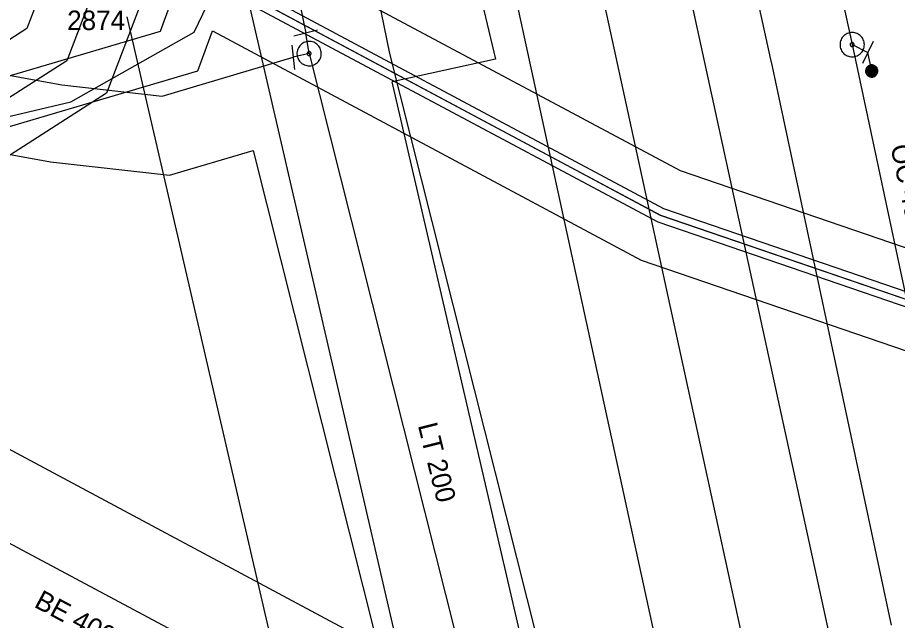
# Model space of a CAD drawing. Extents: x -762993 to -761845, y -975230 to -974501.
# Drawn here: x -762287.32 to -762269.27, y -974997.12 to -974984.74 of the extents above; entities that cross this region are included whole.
import ezdxf

# ---------------------------------------------------------------- set-up
doc = ezdxf.new("R2010")
doc.units = 0
for name, color, linetype in [('IS_CETIN_chranicka', 7, 'Continuous'), ('IS_CETIN_OP', 7, 'Continuous'), ('IS_CETIN_podzem optika zam', 7, 'Continuous'), ('IS_CETIN_podzem out of order', 7, 'Continuous'), ('IS_CEZ-T_parovod', 7, 'Continuous'), ('IS_CEZ-T_parovod OP', 7, 'Continuous'), ('IS_CRA_podzem telekomunikace', 7, 'Continuous'), ('IS_DPmUL_OP', 7, 'Continuous'), ('IS_DPmUL_trakce anotace', 7, 'Continuous'), ('IS_DPmUL_VO vedeni podzem', 7, 'Continuous'), ('IS_SCVK_kanalizace anotace', 7, 'Continuous'), ('IS_SCVK_kanalizace jednotna', 7, 'Continuous'), ('IS_SCVK_kanalizace OP', 7, 'Continuous'), ('IS_SCVK_vodovod anotace', 7, 'Continuous'), ('IS_SCVK_vodovod OP', 7, 'Continuous'), ('IS_SCVK_vodovod privadec', 7, 'Continuous'), ('IS_SCVK_vodovod znaky', 7, 'Continuous')]:
    doc.layers.add(name, color=color, linetype=linetype)

msp = doc.modelspace()

# ---------------------------------------------------------------- linework, layer by layer
at = {"layer": 'IS_CETIN_chranicka'}
for points in [[(-762286.819, -974981.848), (-762283.199, -974983.778), (-762274.07, -974988.662), (-762260.489, -974993.315), (-762251.575, -974995.272), (-762242.453, -974996.331)], [(-762286.961, -974982.112), (-762283.341, -974984.042), (-762274.19, -974988.938), (-762260.571, -974993.605), (-762251.625, -974995.568), (-762242.487, -974996.629)]]:
    msp.add_lwpolyline(points, dxfattribs=at)
at = {"layer": 'IS_CETIN_OP'}
for points in [[(-762282.633, -974983.117), (-762273.729, -974987.88), (-762260.26, -974992.495), (-762251.435, -974994.432), (-762246.779, -974994.973)], [(-762299.477, -974986.662), (-762293.233, -974988.677), (-762283.623, -974985.836), (-762283.324, -974985.015)], [(-762283.324, -974985.015), (-762274.531, -974989.72), (-762260.8, -974994.425), (-762251.765, -974996.408), (-762246.45, -974997.025)]]:
    msp.add_lwpolyline(points, dxfattribs=at)
at = {"layer": 'IS_CETIN_podzem optika zam'}
for points in [[(-762377.62, -974954.57), (-762366.77, -974958.38), (-762363.37, -974959.59), (-762350.74, -974963.98), (-762348.95, -974964.65), (-762339.36, -974968.07), (-762336.01, -974969.53), (-762326.29, -974972.95), (-762323.74, -974973.76), (-762321.62, -974974.46), (-762319.68, -974975.34), (-762318.84, -974976.94), (-762306.74, -974981.28), (-762300.75, -974982.76), (-762292.38, -974985.64), (-762290.68, -974986.06), (-762288.13, -974984.96), (-762286.9, -974983.04), (-762287.05, -974982.43), (-762287.36, -974981.94), (-762286.89, -974981.98), (-762283.27, -974983.91), (-762274.13, -974988.8), (-762260.53, -974993.46)], [(-762299.17, -974985.71), (-762293.22, -974987.63), (-762284.39, -974985.02), (-762281.56, -974977.25), (-762281.87, -974976.53), (-762282.79, -974972.08)]]:
    msp.add_lwpolyline(points, dxfattribs=at)
at = {"layer": 'IS_CETIN_podzem out of order'}
msp.add_lwpolyline([(-762327.23, -974974.06), (-762309.42, -974980.68), (-762296.86, -974985.37), (-762290.2, -974987.41), (-762286.23, -974986.47), (-762283.7, -974985.04), (-762281.71, -974980.9), (-762281.02, -974976.31)], dxfattribs=at)
at = {"layer": 'IS_CEZ-T_parovod'}
msp.add_line((-762277.86, -975004.82), (-762282.64, -974984.16), dxfattribs=at)
at = {"layer": 'IS_CEZ-T_parovod OP'}
for p, q in [((-762280.855, -975002.967), (-762285.076, -974984.724)), ((-762275.663, -975003.227), (-762279.634, -974986.061))]:
    msp.add_line(p, q, dxfattribs=at)
msp.add_lwpolyline([(-762281.54, -974977.193), (-762279.616, -974976.766), (-762277.52, -974985.598), (-762279.634, -974986.061)], dxfattribs=at)
at = {"layer": 'IS_CRA_podzem telekomunikace'}
msp.add_line((-762285.899, -974982.508), (-762276.159, -974987.718), dxfattribs=at)
msp.add_lwpolyline([(-762276.159, -974987.718), (-762274.141, -974988.802), (-762260.544, -974993.454), (-762257.583, -974994.102)], dxfattribs=at)
at = {"layer": 'IS_DPmUL_OP'}
for points in [[(-762286.443, -974983.158), (-762287.13, -974984.968), (-762288.483, -974985.833), (-762292.533, -974985.594), (-762306.491, -974981.186)], [(-762284.649, -974984.068), (-762285.496, -974986.296), (-762287.953, -974987.867), (-762292.899, -974987.576), (-762307.093, -974983.094)]]:
    msp.add_lwpolyline(points, dxfattribs=at)
at = {"layer": 'IS_DPmUL_VO vedeni podzem'}
msp.add_lwpolyline([(-762285.546, -974983.613), (-762286.313, -974985.632), (-762288.218, -974986.85), (-762292.716, -974986.585), (-762306.792, -974982.14)], dxfattribs=at)
at = {"layer": 'IS_SCVK_kanalizace jednotna'}
for points in [[(-762272.009, -974999.487), (-762282.203, -974952.631)], [(-762299.318, -974989.209), (-762270.284, -975004.741)]]:
    msp.add_lwpolyline(points, dxfattribs=at)
at = {"layer": 'IS_SCVK_kanalizace OP'}
msp.add_line((-762298.611, -974987.659), (-762269.759, -975003.094), dxfattribs=at)
for points in [[(-762270.299, -974999.115), (-762280.493, -974952.259)], [(-762273.719, -974999.859), (-762283.913, -974953.003)]]:
    msp.add_lwpolyline(points, dxfattribs=at)
at = {"layer": 'IS_SCVK_vodovod OP'}
for p, q in [((-762279.692, -974985.479), (-762274.766, -975005.04)), ((-762271.863, -974985.652), (-762269.402, -974997.215)), ((-762282.49, -974987.47), (-762277.378, -975007.772))]:
    msp.add_line(p, q, dxfattribs=at)
for points in [[(-762293.748, -974916.96), (-762291.431, -974928.152), (-762279.692, -974985.479)], [(-762286.185, -974918.152), (-762284.45, -974928.304), (-762271.86, -974985.662)], [(-762371.852, -974959.319), (-762366.733, -974961.125), (-762365.959, -974961.392), (-762351.074, -974966.651), (-762348.097, -974967.643), (-762328.082, -974974.681), (-762324.702, -974975.757), (-762322.277, -974976.604), (-762303.577, -974983.171), (-762292.841, -974986.577), (-762286.645, -974987.706), (-762284.209, -974987.979), (-762282.49, -974987.47)]]:
    msp.add_lwpolyline(points, dxfattribs=at)
at = {"layer": 'IS_SCVK_vodovod privadec'}
for points in [[(-762295.315, -974917.284), (-762292.998, -974928.475), (-762281.41, -974985.064)], [(-762284.509, -974917.866), (-762282.781, -974927.978), (-762270.2, -974985.298)], [(-762371.32, -974957.81), (-762366.206, -974959.614), (-762365.432, -974959.881), (-762350.555, -974965.138), (-762347.579, -974966.129), (-762327.574, -974973.164), (-762324.195, -974974.239), (-762321.748, -974975.094), (-762303.07, -974981.653), (-762292.454, -974985.021), (-762286.412, -974986.122), (-762284.353, -974986.353), (-762281.669, -974985.558)], [(-762270.2, -974985.298), (-762267.587, -974997.574)], [(-762281.341, -974985.482), (-762275.528, -975008.565)]]:
    msp.add_lwpolyline(points, dxfattribs=at)
at = {"layer": 'IS_SCVK_vodovod znaky'}
for points in [[(-762281.167, -974985.003), (-762281.653, -974985.124)], [(-762281.341, -974985.482), (-762281.41, -974985.064)], [(-762270.148, -974985.543), (-762270.123, -974985.535), (-762270.098, -974985.526), (-762270.075, -974985.514), (-762270.053, -974985.5), (-762270.033, -974985.484), (-762270.014, -974985.465), (-762269.998, -974985.445), (-762269.984, -974985.423), (-762269.971, -974985.4), (-762269.962, -974985.375), (-762269.955, -974985.35), (-762269.952, -974985.324), (-762269.95, -974985.298), (-762269.952, -974985.272), (-762269.955, -974985.246), (-762269.962, -974985.221), (-762269.971, -974985.196), (-762269.984, -974985.173), (-762269.998, -974985.151), (-762270.014, -974985.131), (-762270.033, -974985.112), (-762270.053, -974985.096), (-762270.075, -974985.081), (-762270.098, -974985.069), (-762270.123, -974985.06), (-762270.148, -974985.053), (-762270.174, -974985.049), (-762270.199, -974985.048), (-762270.226, -974985.05), (-762270.252, -974985.053), (-762270.277, -974985.06), (-762270.302, -974985.07), (-762270.325, -974985.081), (-762270.346, -974985.096), (-762270.367, -974985.112), (-762270.386, -974985.13), (-762270.402, -974985.15), (-762270.417, -974985.173), (-762270.429, -974985.196), (-762270.438, -974985.221), (-762270.444, -974985.246), (-762270.449, -974985.272), (-762270.449, -974985.298), (-762270.448, -974985.324), (-762270.444, -974985.35), (-762270.438, -974985.375), (-762270.428, -974985.4), (-762270.417, -974985.423), (-762270.402, -974985.445), (-762270.386, -974985.465), (-762270.368, -974985.484), (-762270.347, -974985.5), (-762270.325, -974985.514), (-762270.302, -974985.526), (-762270.277, -974985.535), (-762270.252, -974985.543), (-762270.226, -974985.546), (-762270.2, -974985.548), (-762270.174, -974985.546), (-762270.148, -974985.543)], [(-762281.698, -974985.31), (-762281.64, -974985.806)], [(-762281.281, -974985.725), (-762281.256, -974985.717), (-762281.232, -974985.707), (-762281.209, -974985.694), (-762281.188, -974985.68), (-762281.167, -974985.662), (-762281.15, -974985.643), (-762281.134, -974985.622), (-762281.121, -974985.6), (-762281.11, -974985.576), (-762281.101, -974985.552), (-762281.095, -974985.525), (-762281.091, -974985.5), (-762281.091, -974985.474), (-762281.093, -974985.448), (-762281.098, -974985.422), (-762281.106, -974985.397), (-762281.116, -974985.373), (-762281.128, -974985.35), (-762281.143, -974985.329), (-762281.16, -974985.309), (-762281.18, -974985.291), (-762281.201, -974985.275), (-762281.223, -974985.261), (-762281.247, -974985.25), (-762281.271, -974985.242), (-762281.297, -974985.236), (-762281.323, -974985.232), (-762281.349, -974985.232), (-762281.375, -974985.234), (-762281.4, -974985.239), (-762281.426, -974985.247), (-762281.449, -974985.257), (-762281.473, -974985.269), (-762281.494, -974985.284), (-762281.514, -974985.302), (-762281.532, -974985.321), (-762281.548, -974985.341), (-762281.562, -974985.364), (-762281.573, -974985.388), (-762281.581, -974985.412), (-762281.587, -974985.438), (-762281.591, -974985.464), (-762281.591, -974985.49), (-762281.589, -974985.516), (-762281.584, -974985.542), (-762281.576, -974985.567), (-762281.566, -974985.591), (-762281.554, -974985.614), (-762281.539, -974985.635), (-762281.521, -974985.655), (-762281.502, -974985.673), (-762281.481, -974985.689), (-762281.459, -974985.702), (-762281.435, -974985.713), (-762281.41, -974985.722), (-762281.385, -974985.728), (-762281.359, -974985.731), (-762281.333, -974985.731), (-762281.307, -974985.73), (-762281.281, -974985.725)], [(-762270.191, -974985.338), (-762270.187, -974985.337), (-762270.183, -974985.335), (-762270.18, -974985.334), (-762270.176, -974985.331), (-762270.172, -974985.328), (-762270.17, -974985.325), (-762270.167, -974985.322), (-762270.164, -974985.319), (-762270.163, -974985.315), (-762270.161, -974985.311), (-762270.16, -974985.306), (-762270.159, -974985.302), (-762270.159, -974985.298), (-762270.159, -974985.294), (-762270.16, -974985.289), (-762270.16, -974985.285), (-762270.163, -974985.281), (-762270.164, -974985.278), (-762270.167, -974985.274), (-762270.17, -974985.271), (-762270.172, -974985.268), (-762270.176, -974985.265), (-762270.179, -974985.262), (-762270.183, -974985.26), (-762270.187, -974985.259), (-762270.192, -974985.258), (-762270.196, -974985.257), (-762270.199, -974985.257), (-762270.204, -974985.257), (-762270.209, -974985.258), (-762270.213, -974985.258), (-762270.216, -974985.261), (-762270.22, -974985.262), (-762270.224, -974985.265), (-762270.227, -974985.268), (-762270.23, -974985.27), (-762270.233, -974985.274), (-762270.236, -974985.277), (-762270.238, -974985.281), (-762270.239, -974985.285), (-762270.24, -974985.29), (-762270.241, -974985.294), (-762270.241, -974985.298), (-762270.241, -974985.302), (-762270.24, -974985.307), (-762270.239, -974985.311), (-762270.237, -974985.315), (-762270.236, -974985.318), (-762270.233, -974985.322), (-762270.23, -974985.325), (-762270.228, -974985.328), (-762270.224, -974985.331), (-762270.221, -974985.334), (-762270.216, -974985.335), (-762270.213, -974985.337), (-762270.208, -974985.338), (-762270.204, -974985.339), (-762270.2, -974985.339), (-762270.196, -974985.339), (-762270.191, -974985.338)], [(-762270.2, -974985.298), (-762269.879, -974985.46)], [(-762269.767, -974985.236), (-762269.991, -974985.683)], [(-762281.341, -974985.482), (-762281.669, -974985.558)], [(-762281.331, -974985.522), (-762281.327, -974985.521), (-762281.323, -974985.519), (-762281.319, -974985.517), (-762281.316, -974985.514), (-762281.312, -974985.512), (-762281.31, -974985.508), (-762281.307, -974985.505), (-762281.305, -974985.501), (-762281.303, -974985.497), (-762281.302, -974985.493), (-762281.301, -974985.489), (-762281.3, -974985.485), (-762281.3, -974985.481), (-762281.3, -974985.476), (-762281.301, -974985.472), (-762281.302, -974985.468), (-762281.304, -974985.464), (-762281.306, -974985.461), (-762281.309, -974985.457), (-762281.311, -974985.454), (-762281.314, -974985.451), (-762281.318, -974985.448), (-762281.322, -974985.446), (-762281.326, -974985.444), (-762281.329, -974985.443), (-762281.334, -974985.442), (-762281.338, -974985.441), (-762281.342, -974985.441), (-762281.346, -974985.441), (-762281.351, -974985.442), (-762281.355, -974985.443), (-762281.359, -974985.445), (-762281.362, -974985.447), (-762281.366, -974985.45), (-762281.369, -974985.452), (-762281.372, -974985.455), (-762281.375, -974985.459), (-762281.377, -974985.463), (-762281.379, -974985.467), (-762281.38, -974985.471), (-762281.381, -974985.475), (-762281.382, -974985.479), (-762281.382, -974985.483), (-762281.382, -974985.487), (-762281.381, -974985.492), (-762281.38, -974985.496), (-762281.378, -974985.5), (-762281.376, -974985.503), (-762281.373, -974985.507), (-762281.371, -974985.51), (-762281.368, -974985.513), (-762281.364, -974985.516), (-762281.36, -974985.518), (-762281.356, -974985.52), (-762281.352, -974985.521), (-762281.348, -974985.522), (-762281.344, -974985.523), (-762281.34, -974985.523), (-762281.336, -974985.523), (-762281.331, -974985.522)], [(-762269.799, -974985.839), (-762269.879, -974985.46)], [(-762269.925, -974985.839), (-762269.925, -974985.852), (-762269.923, -974985.865), (-762269.92, -974985.878), (-762269.915, -974985.89), (-762269.909, -974985.902), (-762269.902, -974985.913), (-762269.894, -974985.923), (-762269.884, -974985.933), (-762269.874, -974985.941), (-762269.863, -974985.948), (-762269.851, -974985.954), (-762269.839, -974985.959), (-762269.826, -974985.962), (-762269.813, -974985.964), (-762269.8, -974985.966), (-762269.787, -974985.965), (-762269.774, -974985.963), (-762269.761, -974985.96), (-762269.749, -974985.955), (-762269.737, -974985.949), (-762269.726, -974985.942), (-762269.716, -974985.934), (-762269.706, -974985.924), (-762269.698, -974985.914), (-762269.691, -974985.903), (-762269.685, -974985.891), (-762269.68, -974985.879), (-762269.677, -974985.866), (-762269.675, -974985.853), (-762269.673, -974985.84), (-762269.674, -974985.827), (-762269.676, -974985.814), (-762269.679, -974985.801), (-762269.684, -974985.789), (-762269.69, -974985.777), (-762269.697, -974985.766), (-762269.705, -974985.756), (-762269.715, -974985.746), (-762269.725, -974985.738), (-762269.736, -974985.731), (-762269.748, -974985.725), (-762269.76, -974985.72), (-762269.773, -974985.717), (-762269.786, -974985.715), (-762269.799, -974985.714), (-762269.812, -974985.714), (-762269.825, -974985.716), (-762269.838, -974985.719), (-762269.85, -974985.724), (-762269.862, -974985.73), (-762269.873, -974985.737), (-762269.883, -974985.745), (-762269.893, -974985.755), (-762269.901, -974985.765), (-762269.908, -974985.776), (-762269.914, -974985.788), (-762269.919, -974985.8), (-762269.922, -974985.813), (-762269.924, -974985.826), (-762269.925, -974985.839)], [(-762269.905, -974985.839), (-762269.906, -974985.85), (-762269.904, -974985.861), (-762269.901, -974985.872), (-762269.897, -974985.882), (-762269.892, -974985.892), (-762269.886, -974985.901), (-762269.879, -974985.91), (-762269.871, -974985.918), (-762269.862, -974985.925), (-762269.853, -974985.931), (-762269.843, -974985.936), (-762269.833, -974985.94), (-762269.822, -974985.943), (-762269.811, -974985.946), (-762269.8, -974985.946), (-762269.789, -974985.946), (-762269.778, -974985.944), (-762269.767, -974985.941), (-762269.757, -974985.937), (-762269.747, -974985.932), (-762269.738, -974985.926), (-762269.729, -974985.919), (-762269.721, -974985.911), (-762269.714, -974985.902), (-762269.708, -974985.893), (-762269.703, -974985.883), (-762269.699, -974985.873), (-762269.696, -974985.862), (-762269.694, -974985.851), (-762269.693, -974985.84), (-762269.693, -974985.829), (-762269.695, -974985.818), (-762269.698, -974985.807), (-762269.702, -974985.797), (-762269.707, -974985.787), (-762269.713, -974985.778), (-762269.72, -974985.769), (-762269.728, -974985.761), (-762269.737, -974985.754), (-762269.746, -974985.748), (-762269.756, -974985.743), (-762269.766, -974985.739), (-762269.777, -974985.736), (-762269.788, -974985.734), (-762269.799, -974985.734), (-762269.81, -974985.733), (-762269.821, -974985.735), (-762269.832, -974985.738), (-762269.842, -974985.742), (-762269.852, -974985.747), (-762269.861, -974985.753), (-762269.87, -974985.76), (-762269.878, -974985.768), (-762269.885, -974985.777), (-762269.891, -974985.786), (-762269.896, -974985.796), (-762269.9, -974985.806), (-762269.903, -974985.817), (-762269.905, -974985.828), (-762269.905, -974985.839)], [(-762269.886, -974985.839), (-762269.886, -974985.848), (-762269.885, -974985.857), (-762269.882, -974985.866), (-762269.879, -974985.874), (-762269.875, -974985.882), (-762269.87, -974985.89), (-762269.864, -974985.897), (-762269.858, -974985.903), (-762269.851, -974985.909), (-762269.843, -974985.914), (-762269.835, -974985.918), (-762269.827, -974985.921), (-762269.818, -974985.924), (-762269.809, -974985.925), (-762269.8, -974985.927), (-762269.791, -974985.926), (-762269.782, -974985.925), (-762269.773, -974985.922), (-762269.765, -974985.919), (-762269.757, -974985.915), (-762269.749, -974985.91), (-762269.742, -974985.904), (-762269.736, -974985.898), (-762269.73, -974985.891), (-762269.725, -974985.883), (-762269.721, -974985.875), (-762269.718, -974985.867), (-762269.715, -974985.858), (-762269.714, -974985.849), (-762269.712, -974985.84), (-762269.713, -974985.831), (-762269.714, -974985.822), (-762269.717, -974985.813), (-762269.72, -974985.805), (-762269.724, -974985.797), (-762269.729, -974985.789), (-762269.735, -974985.782), (-762269.741, -974985.776), (-762269.748, -974985.77), (-762269.756, -974985.765), (-762269.764, -974985.761), (-762269.772, -974985.758), (-762269.781, -974985.755), (-762269.79, -974985.754), (-762269.799, -974985.753), (-762269.808, -974985.753), (-762269.817, -974985.754), (-762269.826, -974985.757), (-762269.834, -974985.76), (-762269.842, -974985.764), (-762269.85, -974985.769), (-762269.857, -974985.775), (-762269.863, -974985.781), (-762269.869, -974985.788), (-762269.874, -974985.796), (-762269.878, -974985.804), (-762269.881, -974985.812), (-762269.884, -974985.821), (-762269.885, -974985.83), (-762269.886, -974985.839)], [(-762269.866, -974985.839), (-762269.866, -974985.846), (-762269.865, -974985.853), (-762269.864, -974985.86), (-762269.861, -974985.866), (-762269.858, -974985.872), (-762269.854, -974985.878), (-762269.85, -974985.884), (-762269.845, -974985.889), (-762269.839, -974985.893), (-762269.833, -974985.897), (-762269.827, -974985.9), (-762269.821, -974985.903), (-762269.814, -974985.904), (-762269.807, -974985.907), (-762269.8, -974985.907), (-762269.793, -974985.907), (-762269.786, -974985.905), (-762269.779, -974985.904), (-762269.773, -974985.901), (-762269.766, -974985.898), (-762269.761, -974985.894), (-762269.755, -974985.89), (-762269.75, -974985.885), (-762269.746, -974985.879), (-762269.742, -974985.873), (-762269.739, -974985.867), (-762269.736, -974985.861), (-762269.734, -974985.854), (-762269.733, -974985.847), (-762269.732, -974985.84), (-762269.732, -974985.833), (-762269.733, -974985.826), (-762269.735, -974985.819), (-762269.738, -974985.813), (-762269.741, -974985.806), (-762269.745, -974985.801), (-762269.749, -974985.795), (-762269.754, -974985.79), (-762269.76, -974985.786), (-762269.765, -974985.782), (-762269.772, -974985.779), (-762269.778, -974985.776), (-762269.785, -974985.774), (-762269.792, -974985.773), (-762269.799, -974985.773), (-762269.806, -974985.773), (-762269.813, -974985.773), (-762269.82, -974985.775), (-762269.826, -974985.778), (-762269.832, -974985.781), (-762269.838, -974985.785), (-762269.844, -974985.789), (-762269.849, -974985.794), (-762269.853, -974985.8), (-762269.857, -974985.805), (-762269.86, -974985.812), (-762269.863, -974985.818), (-762269.864, -974985.825), (-762269.866, -974985.832), (-762269.866, -974985.839)], [(-762269.846, -974985.839), (-762269.846, -974985.844), (-762269.846, -974985.849), (-762269.845, -974985.854), (-762269.843, -974985.858), (-762269.841, -974985.863), (-762269.838, -974985.867), (-762269.835, -974985.87), (-762269.831, -974985.874), (-762269.828, -974985.877), (-762269.824, -974985.88), (-762269.819, -974985.882), (-762269.815, -974985.884), (-762269.81, -974985.885), (-762269.805, -974985.887), (-762269.8, -974985.887), (-762269.795, -974985.887), (-762269.79, -974985.886), (-762269.785, -974985.885), (-762269.781, -974985.883), (-762269.776, -974985.881), (-762269.772, -974985.878), (-762269.768, -974985.875), (-762269.765, -974985.871), (-762269.762, -974985.868), (-762269.759, -974985.864), (-762269.757, -974985.859), (-762269.755, -974985.855), (-762269.754, -974985.85), (-762269.753, -974985.845), (-762269.752, -974985.84), (-762269.752, -974985.835), (-762269.753, -974985.83), (-762269.754, -974985.825), (-762269.756, -974985.821), (-762269.758, -974985.816), (-762269.761, -974985.812), (-762269.764, -974985.808), (-762269.767, -974985.805), (-762269.771, -974985.802), (-762269.775, -974985.799), (-762269.78, -974985.797), (-762269.784, -974985.795), (-762269.789, -974985.794), (-762269.794, -974985.793), (-762269.799, -974985.793), (-762269.804, -974985.793), (-762269.809, -974985.794), (-762269.814, -974985.794), (-762269.818, -974985.796), (-762269.823, -974985.798), (-762269.827, -974985.801), (-762269.83, -974985.804), (-762269.834, -974985.807), (-762269.837, -974985.811), (-762269.84, -974985.815), (-762269.842, -974985.82), (-762269.844, -974985.824), (-762269.845, -974985.829), (-762269.846, -974985.834), (-762269.846, -974985.839)], [(-762269.826, -974985.839), (-762269.826, -974985.842), (-762269.827, -974985.845), (-762269.826, -974985.847), (-762269.825, -974985.85), (-762269.824, -974985.853), (-762269.822, -974985.855), (-762269.82, -974985.857), (-762269.818, -974985.859), (-762269.816, -974985.861), (-762269.814, -974985.863), (-762269.811, -974985.865), (-762269.808, -974985.866), (-762269.806, -974985.866), (-762269.803, -974985.867), (-762269.8, -974985.867), (-762269.797, -974985.867), (-762269.794, -974985.867), (-762269.791, -974985.866), (-762269.789, -974985.865), (-762269.786, -974985.864), (-762269.784, -974985.862), (-762269.781, -974985.86), (-762269.779, -974985.858), (-762269.778, -974985.856), (-762269.776, -974985.854), (-762269.775, -974985.851), (-762269.773, -974985.848), (-762269.773, -974985.846), (-762269.772, -974985.843), (-762269.771, -974985.84), (-762269.772, -974985.837), (-762269.772, -974985.834), (-762269.773, -974985.831), (-762269.774, -974985.829), (-762269.775, -974985.826), (-762269.777, -974985.824), (-762269.778, -974985.821), (-762269.78, -974985.819), (-762269.783, -974985.818), (-762269.785, -974985.816), (-762269.788, -974985.815), (-762269.79, -974985.814), (-762269.793, -974985.813), (-762269.796, -974985.813), (-762269.799, -974985.812), (-762269.802, -974985.813), (-762269.805, -974985.812), (-762269.807, -974985.814), (-762269.81, -974985.814), (-762269.813, -974985.815), (-762269.815, -974985.817), (-762269.817, -974985.818), (-762269.819, -974985.82), (-762269.821, -974985.823), (-762269.823, -974985.825), (-762269.824, -974985.828), (-762269.825, -974985.83), (-762269.826, -974985.833), (-762269.826, -974985.836), (-762269.826, -974985.839)], [(-762269.807, -974985.839), (-762269.807, -974985.841), (-762269.807, -974985.841), (-762269.806, -974985.841), (-762269.806, -974985.843), (-762269.807, -974985.844), (-762269.805, -974985.844), (-762269.805, -974985.844), (-762269.805, -974985.846), (-762269.805, -974985.846), (-762269.804, -974985.847), (-762269.802, -974985.847), (-762269.802, -974985.847), (-762269.802, -974985.848), (-762269.8, -974985.848), (-762269.8, -974985.848), (-762269.799, -974985.848), (-762269.798, -974985.848), (-762269.798, -974985.847), (-762269.797, -974985.847), (-762269.795, -974985.847), (-762269.795, -974985.846), (-762269.795, -974985.846), (-762269.794, -974985.845), (-762269.794, -974985.845), (-762269.792, -974985.844), (-762269.792, -974985.843), (-762269.791, -974985.842), (-762269.791, -974985.842), (-762269.791, -974985.841), (-762269.791, -974985.84), (-762269.791, -974985.839), (-762269.791, -974985.838), (-762269.791, -974985.838), (-762269.792, -974985.837), (-762269.792, -974985.836), (-762269.793, -974985.835), (-762269.793, -974985.835), (-762269.794, -974985.834), (-762269.794, -974985.834), (-762269.795, -974985.833), (-762269.796, -974985.833), (-762269.797, -974985.832), (-762269.797, -974985.832), (-762269.798, -974985.832), (-762269.799, -974985.832), (-762269.8, -974985.832), (-762269.801, -974985.832), (-762269.801, -974985.832), (-762269.802, -974985.833), (-762269.803, -974985.832), (-762269.804, -974985.834), (-762269.804, -974985.834), (-762269.805, -974985.834), (-762269.805, -974985.834), (-762269.806, -974985.836), (-762269.806, -974985.837), (-762269.806, -974985.838), (-762269.807, -974985.838), (-762269.807, -974985.839), (-762269.807, -974985.839)]]:
    msp.add_lwpolyline(points, dxfattribs=at)

# ---------------------------------------------------------------- texts
at = {"layer": 'IS_DPmUL_trakce anotace'}
msp.add_text('2874', height=0.4, dxfattribs=at).set_placement((-762286.306, -974984.999))
at = {"layer": 'IS_SCVK_kanalizace anotace'}
msp.add_text('BE 400', height=0.4, rotation=332, dxfattribs=at).set_placement((-762287.004, -974996.833))
at = {"layer": 'IS_SCVK_vodovod anotace'}
for s, rotation, p in [('OC 400', 282, (-762269.416, -974987.388)), ('LT 200', 284, (-762279.112, -974993.113))]:
    msp.add_text(s, height=0.4, rotation=rotation, dxfattribs=at).set_placement(p)

doc.saveas('drawing.dxf')
